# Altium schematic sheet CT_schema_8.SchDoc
size 274 x 160 mm
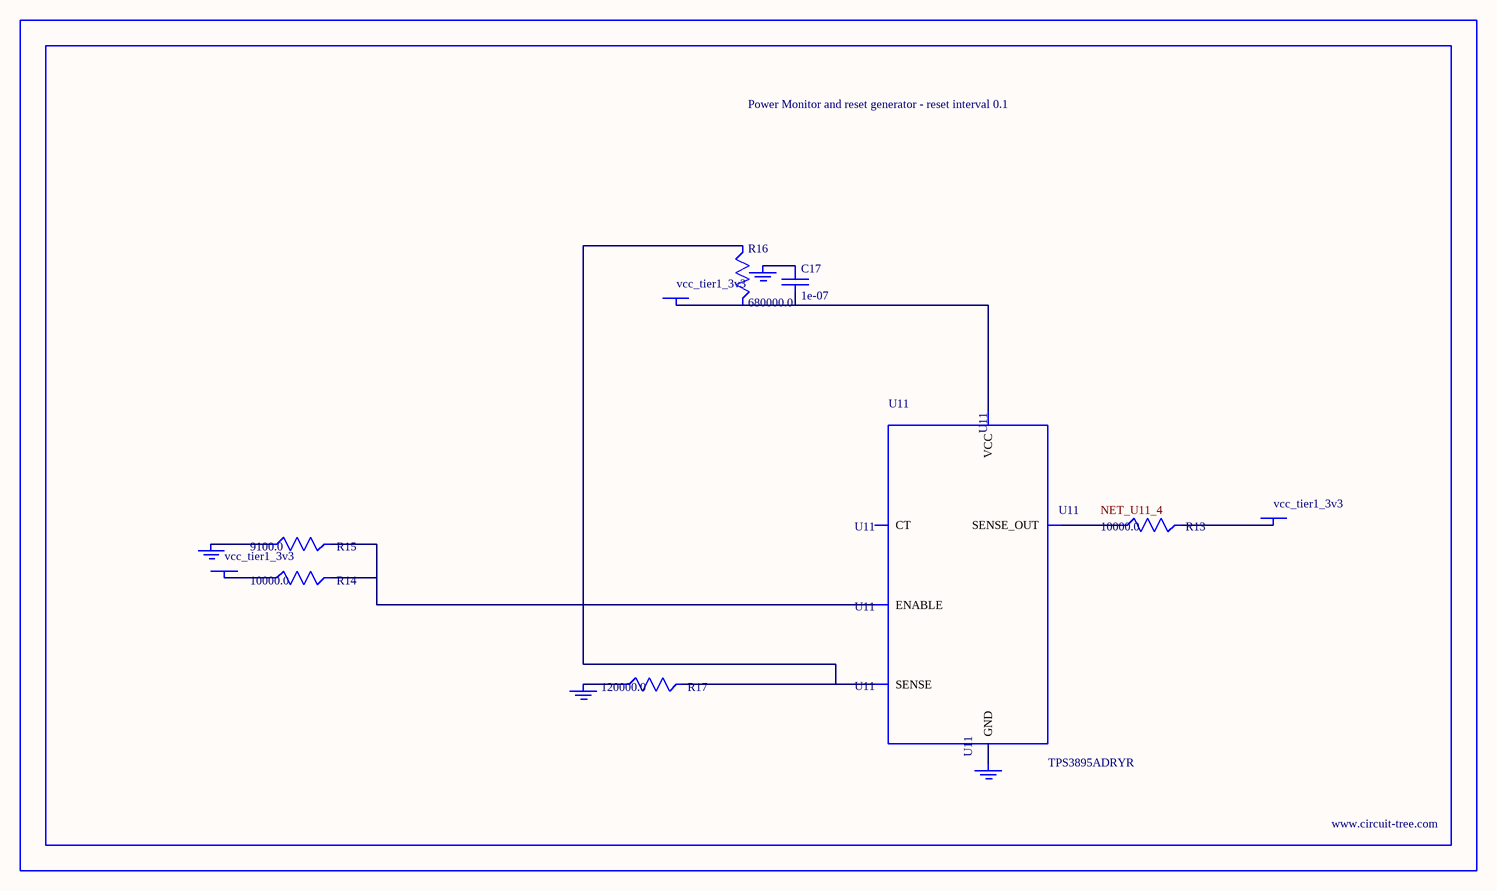
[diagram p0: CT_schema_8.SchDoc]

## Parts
BORDER7  (no value)
C17  1e-07  [C0402]
GND_INSTANCE_7_0  (no value)
GND_INSTANCE_7_1  (no value)
GND_INSTANCE_7_2  (no value)
GND_INSTANCE_7_3  (no value)
POWER_INSTANCE_7_0  vcc_tier1_3v3
POWER_INSTANCE_7_1  vcc_tier1_3v3
POWER_INSTANCE_7_2  vcc_tier1_3v3
R13  10000.0  [R0603]
R14  10000.0  [R0603]
R15  9100.0  [R0603]
R16  680000.0  [R0603]
R17  120000.0  [R0603]
U11  TPS3895ADRYR  [SON-6]

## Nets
NetC17_1: C17.1 GND_INSTANCE_7_2.0(GND)
NetC17_2: C17.2 POWER_INSTANCE_7_2.0(PWR) R16.2 U11.6(VCC)
NetGND_INSTANCE_7_0_0: GND_INSTANCE_7_0.0(GND) R15.1
NetGND_INSTANCE_7_1_0: GND_INSTANCE_7_1.0(GND) R17.1
NetGND_INSTANCE_7_3_0: GND_INSTANCE_7_3.0(GND) U11.2(GND)
NetPOWER_INSTANCE_7_0_0: POWER_INSTANCE_7_0.0(PWR) R14.1
NetPOWER_INSTANCE_7_1_0: POWER_INSTANCE_7_1.0(PWR) R13.2
NetR13_1: R13.1 U11.4(SENSE_OUT)
NetR14_2: R14.2 R15.2 U11.1(ENABLE)
NetR16_1: R16.1 R17.2 U11.3(SENSE)

Not connected (* = marked no-connect by the designer): U11 5(CT)

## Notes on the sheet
- Labels drawn without touching a wire or pin: NET_U11_4

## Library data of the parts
BORDER7 = BORDER_PAGE7
C17 = C0402C104K3RACTU
GND_INSTANCE_7_0-GND_INSTANCE_7_3 = GND
POWER_INSTANCE_7_0-POWER_INSTANCE_7_2 = PWR
R13 R14 = RC0603JR-0710KL
R15 = RC0603JR-079K1L
R16 = RC0603JR-07680KL
R17 = RC0603JR-07120KL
